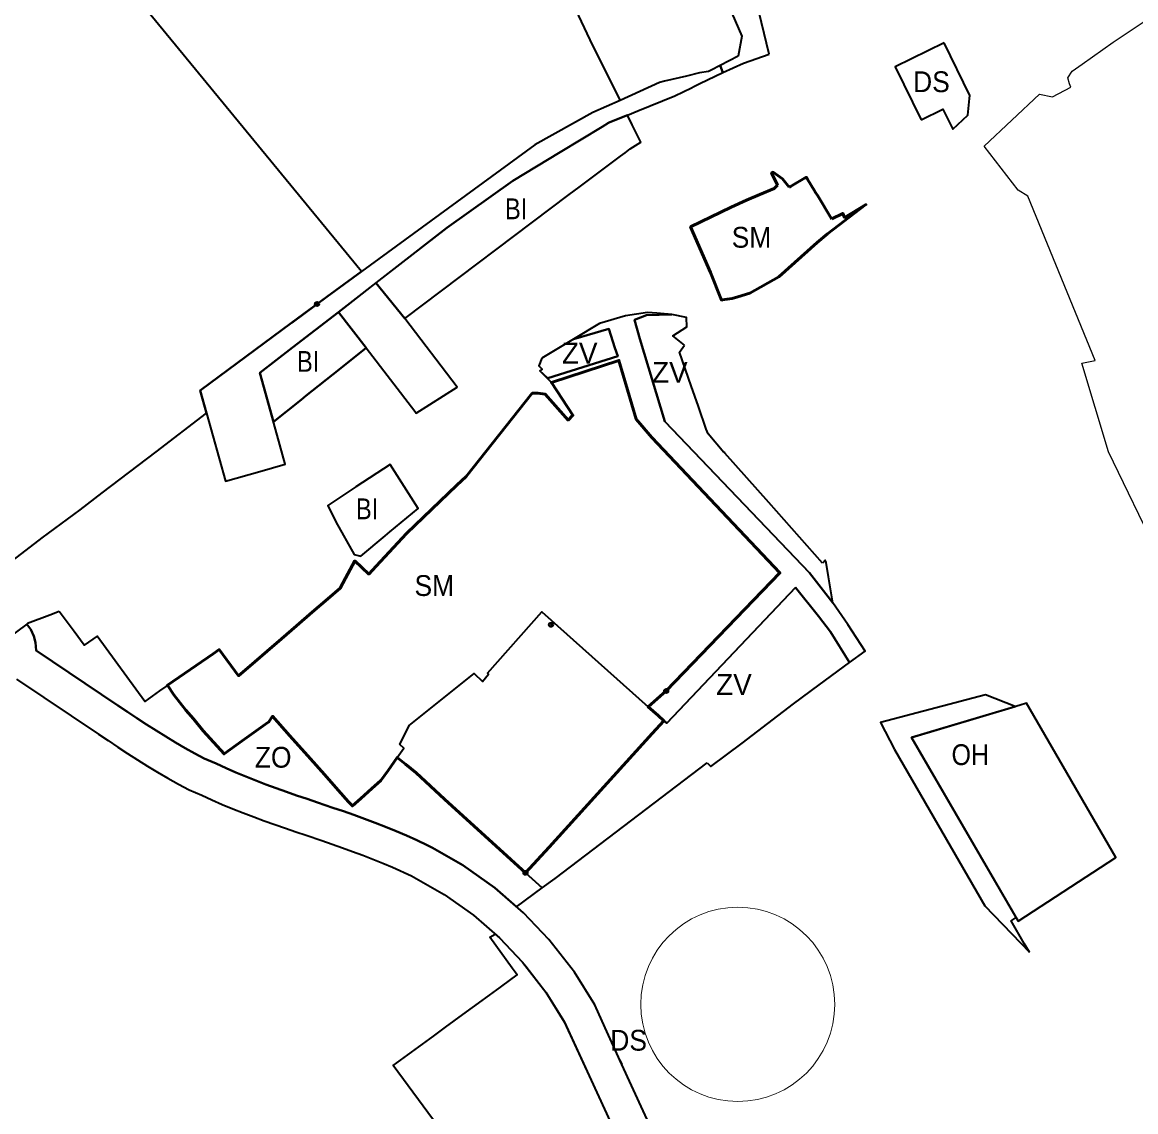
# Model space of a CAD drawing. Extents: x -650276 to -642489, y -1074311 to -1066658.
# Drawn here: x -648072 to -647429, y -1071706 to -1071077 of the extents above; entities that cross this region are included whole.
import ezdxf

# ---------------------------------------------------------------- set-up
doc = ezdxf.new("R2010")
doc.units = 0
doc.header["$LTSCALE"] = 4.8
doc.header["$PDMODE"] = 32
doc.header["$PDSIZE"] = 2.4
for name, color, linetype, lineweight in [('1', 7, 'Continuous', 35), ('10', 7, 'Continuous', 35), ('15', 7, 'Continuous', 35), ('18', 7, 'Continuous', 35), ('2', 7, 'Continuous', 35), ('24', 7, 'Continuous', 35), ('40', 7, 'Continuous', 35), ('42', 7, 'Continuous', 35), ('54', 7, 'Continuous', 35), ('60', 7, 'Continuous', 53), ('61', 7, 'Continuous', 25)]:
    doc.layers.add(name, color=color, linetype=linetype, lineweight=lineweight)
doc.layers.add('62', color=7, linetype='Continuous')

msp = doc.modelspace()

# ---------------------------------------------------------------- linework, layer by layer
at = {"layer": '1'}
msp.add_lwpolyline([(-648001.922, -1071067.83), (-647977.41, -1071049.74), (-647930.7, -1071017.18), (-647911.838, -1071002.919), (-647864.03, -1070969.3), (-647864.03, -1070969.3), (-647818.33, -1070942.91), (-647810.243, -1070939.825), (-647759.52, -1071055.67), (-647757.19, -1071059.66), (-647742.64, -1071090.72), (-647726.74, -1071122.48), (-647742.35, -1071129.43), (-647775.982, -1071148.001), (-647775.982, -1071148.001), (-647875.939, -1071221.104)], close=True, dxfattribs=at)
at = {"layer": '10'}
msp.add_lwpolyline([(-647497.04, -1071595.66), (-647440.67, -1071558.93), (-647492.3, -1071470), (-647495.85, -1071471.06), (-647558.654, -1071489.738)], close=True, dxfattribs=at)
at = {"layer": '15'}
for p, q in [((-647873.25, -1071265.17), (-647845.18, -1071301.54)), ((-647708.429, -1071316.821), (-647717.363, -1071306.29))]:
    msp.add_line(p, q, dxfattribs=at)
for points in [[(-647640.727, -1071095.819), (-647648.106, -1071065.551), (-647654.747, -1071047.095), (-647657.699, -1071038.232), (-647659.01, -1071032.66)], [(-647676.96, -1071039.014), (-647676.9, -1071039.03), (-647676.45, -1071039.22), (-647656.443, -1071085.369), (-647658.55, -1071097.02), (-647669.02, -1071102.33), (-647667.35, -1071106.38), (-647655.47, -1071100.98), (-647640.727, -1071095.819)], [(-647845.18, -1071301.54), (-647844.296, -1071302.757), (-647820.698, -1071287.83), (-647850.956, -1071248.208), (-647867.586, -1071227.694), (-647889.22, -1071244.48), (-647873.25, -1071265.17)], [(-647498.271, -1071593.544), (-647558.654, -1071489.738), (-647498.8, -1071471.94), (-647515.87, -1071465.25), (-647576.471, -1071481.091), (-647568.35, -1071496.656), (-647516.376, -1071586.89), (-647490.561, -1071613.609)], [(-647490.561, -1071613.609), (-647493.6, -1071608.5), (-647501.11, -1071595.45), (-647498.271, -1071593.544)]]:
    msp.add_lwpolyline(points, dxfattribs=at)
for points in [[(-647826.56, -1071195.86), (-647788.66, -1071168.8), (-647761.366, -1071152.304), (-647737.027, -1071137.593), (-647733.38, -1071135.37), (-647732.58, -1071135.04), (-647722.51, -1071130.93), (-647716.51, -1071128.48), (-647695.08, -1071119.72), (-647685.55, -1071115.14), (-647684.15, -1071114.47), (-647680.64, -1071112.77), (-647667.35, -1071106.38), (-647669.02, -1071102.33), (-647674.17, -1071104.97), (-647675.64, -1071105.71), (-647680.82, -1071106.54), (-647688.45, -1071108.38), (-647701.04, -1071111.41), (-647703.96, -1071112.11), (-647726.74, -1071122.48), (-647742.35, -1071129.43), (-647775.982, -1071148.001), (-647895.959, -1071235.746), (-647916.161, -1071250.628), (-647916.208, -1071250.662), (-647968.896, -1071289.779), (-647965.26, -1071302.86), (-647954.38, -1071342), (-647934.51, -1071336.37), (-647919.88, -1071332.23), (-647924.53, -1071315.55), (-647934.6, -1071279.45), (-647915.6, -1071264.95), (-647889.22, -1071244.48)], [(-647625.428, -1071403.267), (-647612.269, -1071419.742), (-647605.292, -1071428.816), (-647594.43, -1071446.543), (-647585.273, -1071440.044), (-647595.335, -1071424.564), (-647603.9, -1071412.1), (-647617.49, -1071394.901), (-647700.816, -1071307.512), (-647715.355, -1071259.885), (-647718.342, -1071248.972), (-647711.447, -1071246.332), (-647696.81, -1071245.79), (-647705.59, -1071245.08), (-647710.94, -1071244.65), (-647723.57, -1071246.66), (-647738.56, -1071251.13), (-647753.647, -1071260.178), (-647733.15, -1071254.081), (-647729.795, -1071265.066), (-647728.006, -1071269.975), (-647768.445, -1071282.6), (-647772.97, -1071278.43), (-647772.07, -1071279.33), (-647766.35, -1071285.11), (-647727.368, -1071272.362), (-647717.363, -1071306.29), (-647708.429, -1071316.821), (-647634.524, -1071394.901), (-647700.078, -1071462.96), (-647710.546, -1071472.023), (-647699.767, -1071481.617)]]:
    msp.add_lwpolyline(points, close=True, dxfattribs=at)
for p in [(-647766.557, -1071424.793), (-647700.078, -1071462.96)]:
    msp.add_point(p, dxfattribs=at)
at = {"layer": '18'}
for points in [[(-647629.09, -1071172.4), (-647632.93, -1071167.71), (-647638.46, -1071163.89), (-647639.32, -1071164.22), (-647635.93, -1071171.22)], [(-647612.695, -1071177.542), (-647613.91, -1071175.57), (-647614.732, -1071174.222), (-647618.446, -1071168.166), (-647618.469, -1071168.129), (-647618.77, -1071167.64), (-647619.264, -1071166.832), (-647619.34, -1071166.709), (-647628.39, -1071172.05), (-647629.09, -1071172.4)], [(-647635.93, -1071171.22), (-647637.87, -1071173.29), (-647646.09, -1071176.68), (-647653.85, -1071179.87), (-647662.634, -1071183.968)], [(-647604.576, -1071190.781), (-647604.888, -1071190.272), (-647612.695, -1071177.542)], [(-647662.634, -1071183.968), (-647686.01, -1071195.35), (-647686.01, -1071195.35)], [(-647674.6, -1071221.71), (-647668.226, -1071237.571), (-647667.77, -1071237.5), (-647661.99, -1071236.62), (-647658.78, -1071235.63), (-647651.93, -1071233.57), (-647635.17, -1071224.18), (-647613.09, -1071204.33), (-647607.02, -1071199.34), (-647584.92, -1071182.54), (-647597.164, -1071189.857), (-647598.215, -1071187.608), (-647604.576, -1071190.781)], [(-647686.01, -1071195.35), (-647686.01, -1071195.35), (-647674.6, -1071221.71)]]:
    msp.add_lwpolyline(points, dxfattribs=at)
msp.add_lwpolyline([(-647974.66, -1071450.62), (-647977.28, -1071452.43), (-647979.88, -1071454.22), (-647982.46, -1071456), (-647985.06, -1071457.79), (-647987.8, -1071459.68), (-647984.07, -1071465.1), (-647977.13, -1071474.05), (-647972.76, -1071479), (-647967.13, -1071486.01), (-647957.07, -1071497.13), (-647955.14, -1071499.23), (-647950.56, -1071495.85), (-647944.81, -1071491.78), (-647939.31, -1071487.88), (-647933.88, -1071484.04), (-647931.17, -1071482.12), (-647929.26, -1071480.77), (-647927.2, -1071477.54), (-647919.22, -1071486.5), (-647881.16, -1071529.25), (-647876.27, -1071524.96), (-647864.69, -1071514.65), (-647851.45, -1071495.96), (-647853.77, -1071493.78), (-647848.4, -1071482.78), (-647810.97, -1071452.92), (-647806.15, -1071457.48), (-647802.53, -1071453.19), (-647803.1, -1071452.66), (-647771.82, -1071417.42), (-647710.546, -1071472.023), (-647700.078, -1071462.96), (-647634.524, -1071394.901), (-647708.429, -1071316.821), (-647717.363, -1071306.29), (-647727.368, -1071272.362), (-647766.35, -1071285.11), (-647753.89, -1071303.94), (-647756.67, -1071306.77), (-647769.85, -1071291.91), (-647774.14, -1071291.34), (-647777.4, -1071291.32), (-647815.95, -1071339.71), (-647820.93, -1071344.25), (-647849.86, -1071372.18), (-647867.45, -1071390.95), (-647871.68, -1071395.59), (-647879.76, -1071387.96), (-647885.05, -1071397.88), (-647888.11, -1071403.61), (-647895.29, -1071409.81), (-647904.3, -1071417.58), (-647911.04, -1071423.39), (-647913.31, -1071425.35), (-647921.96, -1071432.81), (-647946.78, -1071454.23), (-647957.906, -1071439.06)], close=True, dxfattribs=at)
at = {"layer": '2'}
for points in [[(-648091.92, -1071399.07), (-648060.01, -1071374.69), (-648038.18, -1071358.51), (-648025.39, -1071348.76), (-647994.31, -1071325.03), (-647965.26, -1071302.86), (-647966.226, -1071299.385), (-647968.896, -1071289.779), (-647916.208, -1071250.662), (-647895.959, -1071235.746), (-647875.939, -1071221.104), (-648001.922, -1071067.83)], [(-647889.22, -1071244.48), (-647915.6, -1071264.95), (-647934.6, -1071279.45), (-647926.689, -1071307.809), (-647910.73, -1071295.08)], [(-647910.73, -1071295.08), (-647907.92, -1071292.84), (-647888.77, -1071277.56), (-647873.25, -1071265.17), (-647889.22, -1071244.48)]]:
    msp.add_lwpolyline(points, dxfattribs=at)
for points in [[(-647756.03, -1071176.76), (-647750.34, -1071172.5), (-647726.56, -1071154.68), (-647723.79, -1071152.61), (-647720.85, -1071150.41), (-647714.71, -1071146.51), (-647719.73, -1071136.48), (-647722.51, -1071130.93), (-647732.58, -1071135.04), (-647733.38, -1071135.37), (-647737.027, -1071137.593), (-647761.366, -1071152.304), (-647788.66, -1071168.8), (-647826.56, -1071195.86), (-647867.586, -1071227.694), (-647850.956, -1071248.208)], [(-647926.69, -1071307.81), (-647934.6, -1071279.45), (-647889.22, -1071244.48), (-647873.25, -1071265.17), (-647888.77, -1071277.56), (-647907.92, -1071292.84), (-647910.73, -1071295.08)], [(-647879.09, -1071345.3), (-647895.37, -1071355.96), (-647890.7, -1071365.52), (-647880.14, -1071384.32), (-647876.34, -1071385.2), (-647862.25, -1071373.55), (-647859.44, -1071371.23), (-647843.23, -1071357.82), (-647859.31, -1071332.34)]]:
    msp.add_lwpolyline(points, close=True, dxfattribs=at)
msp.add_point((-647901.523, -1071239.822), dxfattribs=at)
at = {"layer": '24'}
for points in [[(-647539.818, -1071089.2), (-647568.01, -1071102.98), (-647553.01, -1071133.68)], [(-647525.1, -1071121.25), (-647524.95, -1071119.68), (-647539.817, -1071089.199)], [(-647553.01, -1071133.68), (-647540.48, -1071127.55), (-647534.851, -1071139.015), (-647526.04, -1071130.94), (-647525.1, -1071121.25)], [(-648063.593, -1071439.723), (-648063.862, -1071435.078), (-648064.838, -1071431.28), (-648066.623, -1071427.592), (-648069.022, -1071424.443), (-648101.203, -1071448.31)], [(-647834.953, -1071553.406), (-647837.929, -1071551.872), (-647843.891, -1071549), (-647849.898, -1071546.282), (-647855.937, -1071543.707), (-647861.998, -1071541.254), (-647868.073, -1071538.911), (-647874.155, -1071536.658), (-647880.233, -1071534.48), (-647886.305, -1071532.36), (-647892.363, -1071530.282), (-647901.28, -1071527.249), (-647907.294, -1071525.204), (-647913.282, -1071523.152), (-647919.238, -1071521.081), (-647925.157, -1071518.976), (-647931.035, -1071516.824), (-647936.866, -1071514.613), (-647942.644, -1071512.329), (-647948.363, -1071509.96), (-647954.016, -1071507.496), (-647959.792, -1071504.833), (-647966.547, -1071501.883), (-647972.035, -1071499.009), (-647977.67, -1071495.885), (-647983.266, -1071492.628), (-647988.829, -1071489.259), (-647994.366, -1071485.79), (-647999.887, -1071482.241), (-648005.399, -1071478.627), (-648010.917, -1071474.963), (-648016.446, -1071471.268), (-648063.593, -1071439.723)], [(-648074.86, -1071456.248), (-648027.562, -1071487.894), (-648022.005, -1071491.607), (-648016.415, -1071495.321), (-648010.777, -1071499.017), (-648005.082, -1071502.678), (-647999.319, -1071506.287), (-647993.478, -1071509.826), (-647987.55, -1071513.275), (-647981.525, -1071516.615), (-647975.201, -1071519.929), (-647967.982, -1071523.081), (-647962.2, -1071525.746), (-647956.187, -1071528.368), (-647950.146, -1071530.869), (-647944.088, -1071533.263), (-647938.019, -1071535.566), (-647931.945, -1071537.788), (-647925.874, -1071539.949), (-647919.808, -1071542.058), (-647913.756, -1071544.132), (-647907.72, -1071546.185), (-647898.827, -1071549.208), (-647892.847, -1071551.26), (-647886.903, -1071553.336), (-647881.001, -1071555.45), (-647875.147, -1071557.619), (-647869.348, -1071559.856), (-647863.611, -1071562.177), (-647857.944, -1071564.594), (-647847.103, -1071569.497)], [(-647725.629, -1071678.373), (-647735.352, -1071657.117), (-647741.34, -1071644.028), (-647753.065, -1071625.201), (-647767.784, -1071606.225), (-647782.408, -1071590.847), (-647798.911, -1071576.526), (-647817.375, -1071563.458), (-647834.953, -1071553.406)], [(-647847.103, -1071569.497), (-647828.141, -1071580.34), (-647811.272, -1071592.28), (-647796.24, -1071605.324), (-647782.97, -1071619.278)], [(-647782.97, -1071619.278), (-647769.498, -1071636.647), (-647758.994, -1071653.513), (-647743.48, -1071687.426), (-647611.514, -1071974.086)], [(-647570.747, -1071972.644), (-647538.922, -1071950.099), (-647551.962, -1071958.049), (-647573.283, -1071969.627), (-647575.415, -1071967.709), (-647577.881, -1071965.979), (-647581.036, -1071964.346), (-647584.363, -1071963.196), (-647588.064, -1071962.51), (-647591.518, -1071962.387), (-647594.731, -1071962.714), (-647725.614, -1071678.405), (-647726.774, -1071675.885), (-647725.629, -1071678.373)]]:
    msp.add_lwpolyline(points, dxfattribs=at)
at = {"layer": '40'}
msp.add_line((-647617.49, -1071394.901), (-647603.9, -1071412.1), dxfattribs=at)
for points in [[(-647696.81, -1071245.79), (-647711.447, -1071246.332), (-647718.342, -1071248.972), (-647715.355, -1071259.885), (-647700.816, -1071307.512), (-647617.49, -1071394.901)], [(-647689.61, -1071263.51), (-647696.35, -1071258.14), (-647688.17, -1071253.06), (-647688.46, -1071247.65), (-647696.81, -1071245.79)], [(-647728.006, -1071269.975), (-647729.795, -1071265.066), (-647733.15, -1071254.081), (-647753.647, -1071260.178), (-647771.76, -1071271.04)], [(-647666.78, -1071325.52), (-647675.85, -1071314.62), (-647677, -1071312.01), (-647681.53, -1071299.02), (-647685.74, -1071286.93), (-647692.45, -1071267.67), (-647689.61, -1071263.51)], [(-647771.76, -1071271.04), (-647773.6, -1071275.43), (-647771.59, -1071277.36), (-647772.97, -1071278.43), (-647768.445, -1071282.6), (-647728.006, -1071269.975)], [(-647609.85, -1071389.21), (-647640.92, -1071354.21), (-647666.21, -1071325.89), (-647666.629, -1071325.351), (-647666.78, -1071325.52)], [(-647603.9, -1071412.1), (-647606.39, -1071397.21), (-647607.77, -1071388.91), (-647608.31, -1071387.63), (-647609.85, -1071389.21)], [(-647625.428, -1071403.267), (-647699.767, -1071481.617), (-647701.415, -1071480.15), (-647708.18, -1071487.57), (-647776.13, -1071562.1)], [(-647676.51, -1071504.34), (-647674.28, -1071506.59), (-647656.27, -1071493.04), (-647626.7, -1071470.46), (-647611.82, -1071459.38), (-647594.43, -1071446.543), (-647605.292, -1071428.816), (-647612.269, -1071419.742), (-647625.428, -1071403.267)], [(-647776.13, -1071562.1), (-647781.31, -1071567.79), (-647771.717, -1071576.551), (-647764.23, -1071571.01), (-647676.51, -1071504.34)]]:
    msp.add_lwpolyline(points, dxfattribs=at)
at = {"layer": '42'}
for p, q in [((-647984.07, -1071465.1), (-647987.8, -1071459.68)), ((-647849.898, -1071546.282), (-647843.891, -1071549))]:
    msp.add_line(p, q, dxfattribs=at)
for points in [[(-648050.25, -1071417.19), (-648055.717, -1071419.253), (-648068.56, -1071424.1), (-648069.022, -1071424.443)], [(-647987.8, -1071459.68), (-647988.713, -1071460.33), (-647992.408, -1071462.858), (-648000.91, -1071469.01), (-648028.31, -1071431.32), (-648035.87, -1071436.62), (-648041.726, -1071428.707), (-648050.25, -1071417.19)], [(-648069.022, -1071424.443), (-648066.623, -1071427.592), (-648064.838, -1071431.28), (-648063.862, -1071435.078), (-648063.593, -1071439.723), (-648016.446, -1071471.268), (-648010.917, -1071474.963), (-648005.399, -1071478.627), (-647999.887, -1071482.241), (-647994.366, -1071485.79)], [(-647944.81, -1071491.78), (-647950.56, -1071495.85), (-647955.14, -1071499.23), (-647957.07, -1071497.13), (-647967.13, -1071486.01), (-647972.76, -1071479), (-647977.13, -1071474.05)], [(-647927.2, -1071477.54), (-647927.2, -1071477.54), (-647929.26, -1071480.77), (-647931.17, -1071482.12), (-647933.88, -1071484.04), (-647939.31, -1071487.88), (-647944.81, -1071491.78)], [(-647855.23, -1071501.297), (-647864.69, -1071514.65), (-647876.27, -1071524.96), (-647881.16, -1071529.25), (-647919.22, -1071486.5), (-647927.2, -1071477.54)], [(-647994.366, -1071485.79), (-647988.829, -1071489.259), (-647983.266, -1071492.628)], [(-647983.266, -1071492.628), (-647977.67, -1071495.885), (-647972.035, -1071499.009), (-647966.547, -1071501.883), (-647959.792, -1071504.833)], [(-647828.024, -1071525.256), (-647844.4, -1071510.2), (-647850.55, -1071505.14), (-647855.23, -1071501.297)], [(-647959.792, -1071504.833), (-647954.016, -1071507.496), (-647948.363, -1071509.96)], [(-647948.363, -1071509.96), (-647942.644, -1071512.329), (-647936.866, -1071514.613)], [(-647936.866, -1071514.613), (-647931.035, -1071516.824), (-647925.157, -1071518.976), (-647919.238, -1071521.081), (-647913.282, -1071523.152)], [(-647781.31, -1071567.79), (-647789.73, -1071560.1), (-647844.4, -1071510.2), (-647828.024, -1071525.256)], [(-647913.282, -1071523.152), (-647907.294, -1071525.204), (-647901.28, -1071527.249)], [(-647901.28, -1071527.249), (-647892.363, -1071530.282), (-647886.305, -1071532.36), (-647880.233, -1071534.48), (-647874.155, -1071536.658), (-647868.073, -1071538.911), (-647861.998, -1071541.254), (-647855.937, -1071543.707), (-647849.898, -1071546.282)], [(-647843.891, -1071549), (-647837.929, -1071551.872), (-647834.953, -1071553.406)], [(-647834.953, -1071553.406), (-647817.375, -1071563.458), (-647798.911, -1071576.526), (-647786.379, -1071587.401), (-647771.717, -1071576.551), (-647781.31, -1071567.79)], [(-647727.85, -1071854.86), (-647857.52, -1071678.92), (-647834.345, -1071661.969), (-647827.42, -1071656.89), (-647817.33, -1071649.51), (-647806.35, -1071641.47), (-647795.76, -1071633.72), (-647794.98, -1071633.15), (-647786.1, -1071626.65), (-647788.942, -1071622.735), (-647801.84, -1071604.97), (-647798.8, -1071603.102), (-647796.24, -1071605.324), (-647782.97, -1071619.278), (-647781.134, -1071621.645), (-647769.498, -1071636.647), (-647758.889, -1071653.742), (-647743.48, -1071687.426), (-647611.514, -1071974.086)]]:
    msp.add_lwpolyline(points, dxfattribs=at)
msp.add_point((-647781.31, -1071567.79), dxfattribs=at)
at = {"layer": '54', "lineweight": 13}
msp.add_circle((-647658.811, -1071643.674), 55.982, dxfattribs=at)
at = {"layer": '60'}
for points in [[(-647629.09, -1071172.4), (-647632.93, -1071167.71), (-647638.46, -1071163.89), (-647639.32, -1071164.22), (-647635.93, -1071171.22)], [(-647612.695, -1071177.542), (-647613.91, -1071175.57), (-647614.732, -1071174.222), (-647618.446, -1071168.166), (-647618.469, -1071168.129), (-647618.77, -1071167.64), (-647619.264, -1071166.832), (-647619.34, -1071166.709), (-647628.39, -1071172.05), (-647629.09, -1071172.4)], [(-647635.93, -1071171.22), (-647637.87, -1071173.29), (-647646.09, -1071176.68), (-647653.85, -1071179.87), (-647662.634, -1071183.968)], [(-647604.576, -1071190.781), (-647604.888, -1071190.272), (-647612.695, -1071177.542)], [(-647662.634, -1071183.968), (-647686.01, -1071195.35), (-647686.01, -1071195.35)], [(-647674.6, -1071221.71), (-647668.226, -1071237.571), (-647667.77, -1071237.5), (-647661.99, -1071236.62), (-647658.78, -1071235.63), (-647651.93, -1071233.57), (-647635.17, -1071224.18), (-647613.09, -1071204.33), (-647607.02, -1071199.34), (-647584.92, -1071182.54), (-647597.164, -1071189.857), (-647598.215, -1071187.608), (-647604.576, -1071190.781)], [(-647686.01, -1071195.35), (-647686.01, -1071195.35), (-647674.6, -1071221.71)]]:
    msp.add_lwpolyline(points, dxfattribs=at)
msp.add_lwpolyline([(-647777.4, -1071291.32), (-647777.4, -1071291.32), (-647774.14, -1071291.34), (-647769.85, -1071291.91), (-647756.67, -1071306.77), (-647753.89, -1071303.94), (-647766.35, -1071285.11), (-647727.368, -1071272.362), (-647717.363, -1071306.29), (-647708.429, -1071316.821), (-647634.524, -1071394.901), (-647700.078, -1071462.96), (-647710.546, -1071472.023), (-647704.78, -1071477.1), (-647701.415, -1071480.15), (-647708.18, -1071487.57), (-647767.575, -1071553.083), (-647781.31, -1071567.79), (-647789.73, -1071560.1), (-647828.024, -1071525.256), (-647844.4, -1071510.2), (-647850.55, -1071505.14), (-647855.23, -1071501.297), (-647860.576, -1071508.843), (-647864.69, -1071514.65), (-647869.922, -1071519.269), (-647876.29, -1071524.89), (-647881.16, -1071529.25), (-647883.31, -1071526.83), (-647889.29, -1071520.11), (-647897.27, -1071511.15), (-647905.25, -1071502.19), (-647917.23, -1071488.75), (-647927.2, -1071477.54), (-647929.26, -1071480.77), (-647931.17, -1071482.12), (-647936.59, -1071485.96), (-647944.81, -1071491.78), (-647955.14, -1071499.23), (-647967.13, -1071486.01), (-647972.76, -1071479), (-647977.13, -1071474.05), (-647984.07, -1071465.1), (-647987.8, -1071459.68), (-647961.4, -1071441.47), (-647957.906, -1071439.06), (-647946.78, -1071454.23), (-647937.43, -1071446.16), (-647930.38, -1071440.08), (-647921.96, -1071432.81), (-647913.31, -1071425.35), (-647904.3, -1071417.58), (-647895.29, -1071409.81), (-647888.11, -1071403.61), (-647885.05, -1071397.88), (-647879.76, -1071387.96), (-647871.68, -1071395.59), (-647867.45, -1071390.95), (-647849.86, -1071372.18), (-647820.93, -1071344.25), (-647815.474, -1071339.22)], close=True, dxfattribs=at)
at = {"layer": '61'}
msp.add_lwpolyline([(-647415.97, -1071385.01), (-647445, -1071324.99), (-647460.28, -1071274.02), (-647452.69, -1071272.32), (-647491.56, -1071177.65), (-647497.03, -1071174.18), (-647516.65, -1071148.87), (-647484.84, -1071118.8), (-647477.3, -1071120.38), (-647466.6, -1071114.88), (-647467.47, -1071112.93), (-647468.47, -1071109.42), (-647465.83, -1071105.54), (-647460.06, -1071101.57), (-647442.36, -1071088.82), (-647406.52, -1071065.05)], dxfattribs=at)

# ---------------------------------------------------------------- texts
at = {"layer": '62'}
for s, width, p in [('DS', 0.95, (-647557.693, -1071117.661)), ('BI', 0.85, (-647793.1, -1071190.942)), ('SM', 0.95, (-647662.328, -1071207.374)), ('BI', 0.85, (-647913.1, -1071278.942)), ('BI', 0.85, (-647879.1, -1071363.942)), ('SM', 0.95, (-647845.307, -1071408.18)), ('ZO', 0.95, (-647937.423, -1071507.188)), ('OH', 0.9, (-647535.508, -1071505.684)), ('DS', 0.95, (-647732.378, -1071670.379))]:
    msp.add_text(s, height=12, dxfattribs=dict(at, width=width)).set_placement(p)
for p in [(-647760.241, -1071274.214), (-647708.241, -1071285.214), (-647671.241, -1071465.214)]:
    msp.add_text('ZV', height=12, dxfattribs=at).set_placement(p)

doc.saveas('drawing.dxf')
